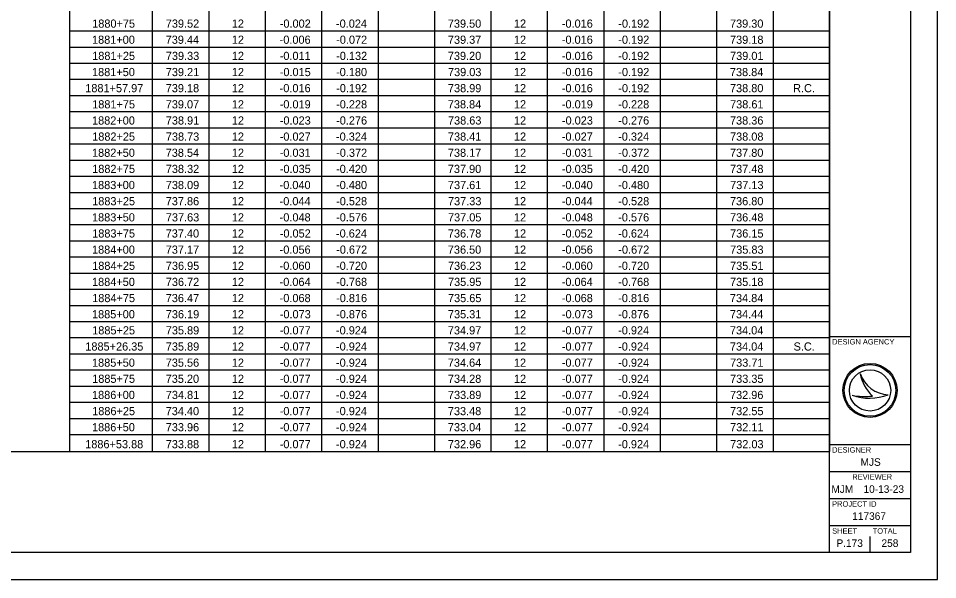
# Model space of a CAD drawing. Extents: x -174 to 34, y 0 to 22.
# Drawn here: x 17 to 34, y 0 to 10.38 of the extents above; entities that cross this region are included whole.
import ezdxf

# ---------------------------------------------------------------- set-up
doc = ezdxf.new("R2010")
doc.units = 0
for name, color, linetype in [('Default', 7, 'Continuous'), ('SH_Border', 7, 'Continuous'), ('SH_Cut_Line', 7, 'Continuous'), ('SH_Data', 7, 'Continuous')]:
    doc.layers.add(name, color=color, linetype=linetype)

msp = doc.modelspace()

# ---------------------------------------------------------------- linework, layer by layer
at = {"layer": 'Default'}
for p, q in [((17.947, 21.5), (17.947, 2.37)), ((32, 21.5), (32, 2.37)), ((19.477, 18.513), (19.477, 2.37)), ((20.521, 18.513), (20.521, 2.37)), ((21.564, 18.513), (21.564, 2.37)), ((22.608, 18.513), (22.608, 2.37)), ((23.651, 18.513), (23.651, 2.37)), ((24.695, 18.513), (24.695, 2.37)), ((25.739, 18.513), (25.739, 2.37)), ((26.782, 18.513), (26.782, 2.37)), ((27.826, 18.513), (27.826, 2.37)), ((28.869, 18.513), (28.869, 2.37)), ((29.913, 18.513), (29.913, 2.37)), ((30.956, 18.513), (30.956, 2.37)), ((17.947, 10.151), (32, 10.151)), ((17.947, 9.852), (32, 9.852)), ((17.947, 9.553), (32, 9.553)), ((17.947, 9.255), (32, 9.255)), ((17.947, 8.956), (32, 8.956)), ((17.947, 8.657), (32, 8.657)), ((17.947, 8.359), (32, 8.359)), ((17.947, 8.06), (32, 8.06)), ((17.947, 7.761), (32, 7.761)), ((17.947, 7.463), (32, 7.463)), ((17.947, 7.164), (32, 7.164)), ((17.947, 6.865), (32, 6.865)), ((17.947, 6.567), (32, 6.567)), ((17.947, 6.268), (32, 6.268)), ((17.947, 5.969), (32, 5.969)), ((17.947, 5.671), (32, 5.671)), ((17.947, 5.372), (32, 5.372)), ((17.947, 5.073), (32, 5.073)), ((17.947, 4.775), (32, 4.775)), ((17.947, 4.476), (32, 4.476)), ((17.947, 4.177), (32, 4.177)), ((17.947, 3.879), (32, 3.879)), ((17.947, 3.58), (32, 3.58)), ((17.947, 3.281), (32, 3.281)), ((17.947, 2.983), (32, 2.983)), ((17.947, 2.684), (32, 2.684)), ((1.5, 2.37), (32, 2.37))]:
    msp.add_line(p, q, dxfattribs=at)
at = {"layer": 'SH_Border'}
for p, q in [((32, 0.5), (32, 21.5)), ((32, 4.5), (33.5, 4.5)), ((32, 2.5), (33.5, 2.5)), ((32, 2), (33.5, 2)), ((32, 1.5), (33.5, 1.5)), ((32, 1), (33.5, 1))]:
    msp.add_line(p, q, dxfattribs=at)
msp.add_lwpolyline([(1.5, 21.5), (33.5, 21.5), (33.5, 0.5), (1.5, 0.5)], close=True, dxfattribs=at)
at = {"layer": 'SH_Cut_Line'}
msp.add_lwpolyline([(0, 0), (34, 0), (34, 22), (0, 22)], close=True, dxfattribs=at)
at = {"layer": 'SH_Data'}
for p, q in [((32.567, 3.81), (32.567, 3.81)), ((32.417, 3.41), (32.417, 3.41)), ((32.75, 3.5), (32.75, 3.5)), ((33.087, 3.419), (33.087, 3.419)), ((32.75, 0.5), (32.75, 0.8)), ((32.375, 0.675), (32.375, 0.675))]:
    msp.add_line(p, q, dxfattribs=at)
for radius in [0.5, 0.477, 0.477, 0.382]:
    msp.add_circle((32.75, 3.5), radius, dxfattribs=at)
for centre, radius, start, end in [((33.116, 3.998), 0.58, 198.9257, 198.9319), ((33.347, 3.97), 0.796, 191.6379, 191.6421), ((33.116, 3.998), 0.58, 198.9319, 267.1657), ((33.347, 3.97), 0.796, 191.6421, 226.0947), ((32.739, 4.37), 1.013, 251.4576, 290.0832), ((32.648, 4.654), 1.266, 259.4964, 259.4995), ((32.739, 4.37), 1.013, 251.4527, 251.4576), ((32.648, 4.654), 1.266, 259.4995, 276.6672)]:
    msp.add_arc(centre, radius, start, end, dxfattribs=at)

# ---------------------------------------------------------------- texts
at = {"layer": 'Default'}
for s, p in [('1880+75', (18.365, 10.21)), ('739.52', (19.726, 10.21)), ('12', (20.947, 10.21)), ('-0.002', (21.834, 10.21)), ('-0.024', (22.874, 10.21)), ('739.50', (24.942, 10.21)), ('12', (26.165, 10.21)), ('-0.016', (27.05, 10.21)), ('-0.192', (28.095, 10.21)), ('739.30', (30.16, 10.21)), ('1881+00', (18.362, 9.912)), ('739.44', (19.724, 9.912)), ('12', (20.947, 9.912)), ('-0.006', (21.832, 9.912)), ('-0.072', (22.877, 9.912)), ('739.37', (24.943, 9.912)), ('12', (26.165, 9.912)), ('-0.016', (27.05, 9.912)), ('-0.192', (28.095, 9.912)), ('739.18', (30.161, 9.912)), ('1881+25', (18.365, 9.613)), ('739.33', (19.727, 9.613)), ('12', (20.947, 9.613)), ('-0.011', (21.833, 9.613)), ('-0.132', (22.877, 9.613)), ('739.20', (24.942, 9.613)), ('12', (26.165, 9.613)), ('-0.016', (27.05, 9.613)), ('-0.192', (28.095, 9.613)), ('739.01', (30.162, 9.613)), ('1881+50', (18.362, 9.314)), ('739.21', (19.726, 9.314)), ('12', (20.947, 9.314)), ('-0.015', (21.834, 9.314)), ('-0.180', (22.875, 9.314)), ('739.03', (24.945, 9.314)), ('12', (26.165, 9.314)), ('-0.016', (27.05, 9.314)), ('-0.192', (28.095, 9.314)), ('738.84', (30.159, 9.314)), ('1881+57.97', (18.237, 9.016)), ('739.18', (19.725, 9.016)), ('12', (20.947, 9.016)), ('-0.016', (21.832, 9.016)), ('-0.192', (22.877, 9.016)), ('738.99', (24.944, 9.016)), ('12', (26.165, 9.016)), ('-0.016', (27.05, 9.016)), ('-0.192', (28.095, 9.016)), ('738.80', (30.16, 9.016)), ('R.C.', (31.328, 9.016)), ('1881+75', (18.365, 8.717)), ('739.07', (19.725, 8.717)), ('12', (20.947, 8.717)), ('-0.019', (21.833, 8.717)), ('-0.228', (22.876, 8.717)), ('738.84', (24.942, 8.717)), ('12', (26.165, 8.717)), ('-0.019', (27.051, 8.717)), ('-0.228', (28.094, 8.717)), ('738.61', (30.162, 8.717)), ('1882+00', (18.362, 8.418)), ('738.91', (19.726, 8.418)), ('12', (20.947, 8.418)), ('-0.023', (21.834, 8.418)), ('-0.276', (22.876, 8.418)), ('738.63', (24.945, 8.418)), ('12', (26.165, 8.418)), ('-0.023', (27.052, 8.418)), ('-0.276', (28.093, 8.418)), ('738.36', (30.16, 8.418)), ('1882+25', (18.365, 8.12)), ('738.73', (19.727, 8.12)), ('12', (20.947, 8.12)), ('-0.027', (21.833, 8.12)), ('-0.324', (22.874, 8.12)), ('738.41', (24.944, 8.12)), ('12', (26.165, 8.12)), ('-0.027', (27.05, 8.12)), ('-0.324', (28.092, 8.12)), ('738.08', (30.161, 8.12)), ('1882+50', (18.362, 7.821)), ('738.54', (19.724, 7.821)), ('12', (20.947, 7.821)), ('-0.031', (21.833, 7.821)), ('-0.372', (22.877, 7.821)), ('738.17', (24.943, 7.821)), ('12', (26.165, 7.821)), ('-0.031', (27.051, 7.821)), ('-0.372', (28.095, 7.821)), ('737.80', (30.16, 7.821)), ('1882+75', (18.365, 7.522)), ('738.32', (19.726, 7.522)), ('12', (20.947, 7.522)), ('-0.035', (21.834, 7.522)), ('-0.420', (22.875, 7.522)), ('737.90', (24.942, 7.522)), ('12', (26.165, 7.522)), ('-0.035', (27.052, 7.522)), ('-0.420', (28.093, 7.522)), ('737.48', (30.161, 7.522)), ('1883+00', (18.362, 7.224)), ('738.09', (19.726, 7.224)), ('12', (20.947, 7.224)), ('-0.040', (21.831, 7.224)), ('-0.480', (22.875, 7.224)), ('737.61', (24.944, 7.224)), ('12', (26.165, 7.224)), ('-0.040', (27.049, 7.224)), ('-0.480', (28.093, 7.224)), ('737.13', (30.163, 7.224)), ('1883+25', (18.365, 6.925)), ('737.86', (19.725, 6.925)), ('12', (20.947, 6.925)), ('-0.044', (21.831, 6.925)), ('-0.528', (22.876, 6.925)), ('737.33', (24.945, 6.925)), ('12', (26.165, 6.925)), ('-0.044', (27.049, 6.925)), ('-0.528', (28.094, 6.925)), ('736.80', (30.16, 6.925)), ('1883+50', (18.362, 6.626)), ('737.63', (19.727, 6.626)), ('12', (20.947, 6.626)), ('-0.048', (21.832, 6.626)), ('-0.576', (22.876, 6.626)), ('737.05', (24.945, 6.626)), ('12', (26.165, 6.626)), ('-0.048', (27.05, 6.626)), ('-0.576', (28.093, 6.626)), ('736.48', (30.161, 6.626)), ('1883+75', (18.365, 6.328)), ('737.40', (19.724, 6.328)), ('12', (20.947, 6.328)), ('-0.052', (21.834, 6.328)), ('-0.624', (22.874, 6.328)), ('736.78', (24.943, 6.328)), ('12', (26.165, 6.328)), ('-0.052', (27.051, 6.328)), ('-0.624', (28.092, 6.328)), ('736.15', (30.162, 6.328)), ('1884+00', (18.362, 6.029)), ('737.17', (19.725, 6.029)), ('12', (20.947, 6.029)), ('-0.056', (21.832, 6.029)), ('-0.672', (22.877, 6.029)), ('736.50', (24.942, 6.029)), ('12', (26.165, 6.029)), ('-0.056', (27.05, 6.029)), ('-0.672', (28.095, 6.029)), ('735.83', (30.163, 6.029)), ('1884+25', (18.365, 5.73)), ('736.95', (19.727, 5.73)), ('12', (20.947, 5.73)), ('-0.060', (21.831, 5.73)), ('-0.720', (22.875, 5.73)), ('736.23', (24.945, 5.73)), ('12', (26.165, 5.73)), ('-0.060', (27.049, 5.73)), ('-0.720', (28.093, 5.73)), ('735.51', (30.162, 5.73)), ('1884+50', (18.362, 5.432)), ('736.72', (19.726, 5.432)), ('12', (20.947, 5.432)), ('-0.064', (21.831, 5.432)), ('-0.768', (22.876, 5.432)), ('735.95', (24.945, 5.432)), ('12', (26.165, 5.432)), ('-0.064', (27.049, 5.432)), ('-0.768', (28.094, 5.432)), ('735.18', (30.161, 5.432)), ('1884+75', (18.365, 5.133)), ('736.47', (19.725, 5.133)), ('12', (20.947, 5.133)), ('-0.068', (21.832, 5.133)), ('-0.816', (22.876, 5.133)), ('735.65', (24.945, 5.133)), ('12', (26.165, 5.133)), ('-0.068', (27.05, 5.133)), ('-0.816', (28.093, 5.133)), ('734.84', (30.159, 5.133)), ('1885+00', (18.362, 4.834)), ('736.19', (19.726, 4.834)), ('12', (20.947, 4.834)), ('-0.073', (21.834, 4.834)), ('-0.876', (22.876, 4.834)), ('735.31', (24.944, 4.834)), ('12', (26.165, 4.834)), ('-0.073', (27.052, 4.834)), ('-0.876', (28.093, 4.834)), ('734.44', (30.159, 4.834)), ('1885+25', (18.365, 4.536)), ('735.89', (19.726, 4.536)), ('12', (20.947, 4.536)), ('-0.077', (21.833, 4.536)), ('-0.924', (22.874, 4.536)), ('734.97', (24.943, 4.536)), ('12', (26.165, 4.536)), ('-0.077', (27.05, 4.536)), ('-0.924', (28.092, 4.536)), ('734.04', (30.159, 4.536)), ('1885+26.35', (18.238, 4.237)), ('735.89', (19.726, 4.237)), ('12', (20.947, 4.237)), ('-0.077', (21.833, 4.237)), ('-0.924', (22.874, 4.237)), ('734.97', (24.943, 4.237)), ('12', (26.165, 4.237)), ('-0.077', (27.05, 4.237)), ('-0.924', (28.092, 4.237)), ('734.04', (30.159, 4.237)), ('S.C.', (31.336, 4.237)), ('1885+50', (18.362, 3.938)), ('735.56', (19.725, 3.938)), ('12', (20.947, 3.938)), ('-0.077', (21.833, 3.938)), ('-0.924', (22.874, 3.938)), ('734.64', (24.942, 3.938)), ('12', (26.165, 3.938)), ('-0.077', (27.05, 3.938)), ('-0.924', (28.092, 3.938)), ('733.71', (30.162, 3.938)), ('1885+75', (18.365, 3.64)), ('735.20', (19.724, 3.64)), ('12', (20.947, 3.64)), ('-0.077', (21.833, 3.64)), ('-0.924', (22.874, 3.64)), ('734.28', (24.943, 3.64)), ('12', (26.165, 3.64)), ('-0.077', (27.05, 3.64)), ('-0.924', (28.092, 3.64)), ('733.35', (30.162, 3.64)), ('1886+00', (18.362, 3.341)), ('734.81', (19.726, 3.341)), ('12', (20.947, 3.341)), ('-0.077', (21.833, 3.341)), ('-0.924', (22.874, 3.341)), ('733.89', (24.944, 3.341)), ('12', (26.165, 3.341)), ('-0.077', (27.05, 3.341)), ('-0.924', (28.092, 3.341)), ('732.96', (30.16, 3.341)), ('1886+25', (18.365, 3.042)), ('734.40', (19.724, 3.042)), ('12', (20.947, 3.042)), ('-0.077', (21.833, 3.042)), ('-0.924', (22.874, 3.042)), ('733.48', (24.943, 3.042)), ('12', (26.165, 3.042)), ('-0.077', (27.05, 3.042)), ('-0.924', (28.092, 3.042)), ('732.55', (30.162, 3.042)), ('1886+50', (18.362, 2.744)), ('733.96', (19.725, 2.744)), ('12', (20.947, 2.744)), ('-0.077', (21.833, 2.744)), ('-0.924', (22.874, 2.744)), ('733.04', (24.942, 2.744)), ('12', (26.165, 2.744)), ('-0.077', (27.05, 2.744)), ('-0.924', (28.092, 2.744)), ('732.11', (30.162, 2.744)), ('1886+53.88', (18.236, 2.43)), ('733.88', (19.725, 2.43)), ('12', (20.947, 2.43)), ('-0.077', (21.833, 2.43)), ('-0.924', (22.874, 2.43)), ('732.96', (24.943, 2.43)), ('12', (26.165, 2.43)), ('-0.077', (27.05, 2.43)), ('-0.924', (28.092, 2.43)), ('732.03', (30.163, 2.43))]:
    msp.add_text(s, height=0.1511, dxfattribs=at).set_placement(p)
at = {"layer": 'SH_Data'}
for s, height, p in [('DESIGN AGENCY', 0.1, (32.05, 4.35)), ('DESIGNER', 0.1, (32.05, 2.35)), ('MJS', 0.14, (32.574, 2.105)), ('REVIEWER', 0.1, (32.422, 1.85)), ('MJM', 0.14, (32.035, 1.605)), ('10-13-23', 0.14, (32.629, 1.605)), ('PROJECT ID', 0.1, (32.05, 1.35)), ('117367', 0.14, (32.42, 1.105)), ('SHEET', 0.1, (32.05, 0.85)), ('TOTAL', 0.1, (32.8, 0.85)), ('P.173', 0.14, (32.129, 0.605)), ('258', 0.14, (32.962, 0.605))]:
    msp.add_text(s, height=height, dxfattribs=at).set_placement(p)

doc.saveas('drawing.dxf')
